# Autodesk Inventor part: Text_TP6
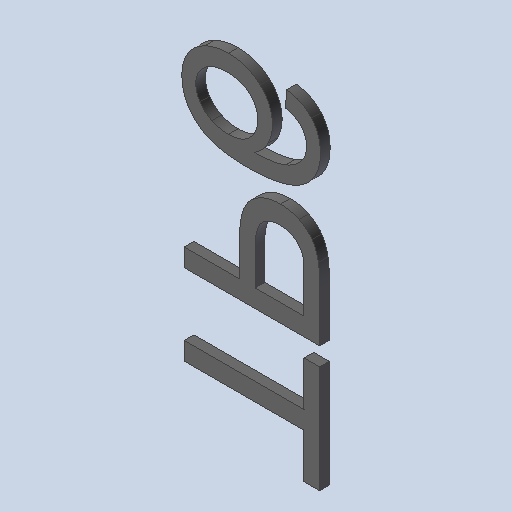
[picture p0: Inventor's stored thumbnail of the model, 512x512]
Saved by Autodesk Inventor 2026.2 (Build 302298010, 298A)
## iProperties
Created: 2026-10
Part Number: Text_TP6
Material: Générique
Document SubType Name: Modeling
Designer: mel
Density: 1 g/cm^3
Appearance: Par défaut
Author: mel
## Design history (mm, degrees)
feature "Base1"
feature "Base2"
feature "Base3"
node "Solide1"
node "Solide2"
node "Solide3"
